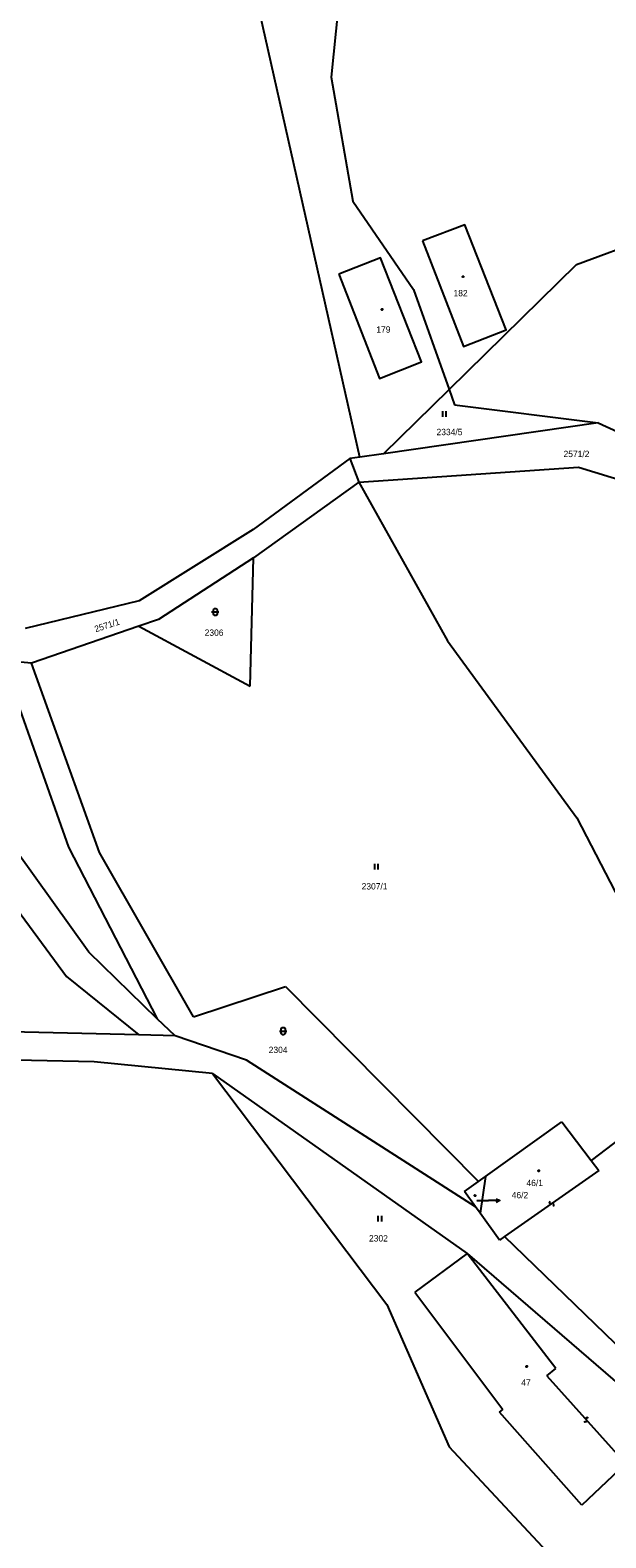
# Model space of a CAD drawing. Extents: x -747792 to -745414, y -1093712 to -1091463.
# Drawn here: x -746775.5 to -746698.3, y -1093052.6 to -1092850.4 of the extents above; entities that cross this region are included whole.
import ezdxf

# ---------------------------------------------------------------- set-up
doc = ezdxf.new("R2010")
doc.units = 0
for name, color, linetype in [('Budovy', 7, 'Continuous'), ('Doplňkové značky', 7, 'Continuous'), ('Koleje_dopravní prvky', 7, 'Continuous'), ('Kultury', 7, 'Continuous'), ('Ploty_opěrné zdi', 7, 'Continuous'), ('Stromy_porost', 7, 'Continuous')]:
    doc.layers.add(name, color=color, linetype=linetype)

msp = doc.modelspace()

# ---------------------------------------------------------------- linework, layer by layer
at = {"layer": 'Budovy'}
for points in [[(-746720.18, -1092901.53), (-746720.18, -1092902.28)], [(-746719.68, -1092902.28), (-746719.68, -1092901.53)], [(-746751.18, -1092928.44), (-746750.55, -1092928.44), (-746750.18, -1092928.44)], [(-746729.33, -1092962.21), (-746729.33, -1092962.96)], [(-746728.83, -1092962.96), (-746728.83, -1092962.21)], [(-746742.07, -1092984.65), (-746741.43, -1092984.65), (-746741.07, -1092984.65)], [(-746728.85, -1093009.42), (-746728.85, -1093010.17)], [(-746728.35, -1093010.17), (-746728.35, -1093009.42)]]:
    msp.add_lwpolyline(points, dxfattribs=at)
for points in [[(-746750.93, -1092928.19), (-746750.88, -1092928.04), (-746750.76, -1092927.96), (-746750.6, -1092927.96), (-746750.48, -1092928.04), (-746750.43, -1092928.19), (-746750.43, -1092928.69), (-746750.48, -1092928.83), (-746750.6, -1092928.92), (-746750.76, -1092928.92), (-746750.88, -1092928.83), (-746750.93, -1092928.69)], [(-746741.82, -1092984.4), (-746741.77, -1092984.26), (-746741.65, -1092984.17), (-746741.49, -1092984.17), (-746741.36, -1092984.26), (-746741.32, -1092984.4), (-746741.32, -1092984.9), (-746741.36, -1092985.04), (-746741.49, -1092985.13), (-746741.65, -1092985.13), (-746741.77, -1092985.04), (-746741.82, -1092984.9)]]:
    msp.add_lwpolyline(points, close=True, dxfattribs=at)
at = {"layer": 'Doplňkové značky'}
for points in [[(-746715.59, -1093007.35), (-746714.01, -1093007.37)], [(-746712.51, -1093007.39), (-746714.01, -1093007.37)], [(-746713.01, -1093007.13), (-746712.51, -1093007.39), (-746713.01, -1093007.63)]]:
    msp.add_lwpolyline(points, dxfattribs=at)
at = {"layer": 'Kultury'}
for points in [[(-746700.24, -1093001.99), (-746699.21, -1093003.36)], [(-746699.21, -1093003.36), (-746711.87, -1093012.22)], [(-746705.35, -1093008.11), (-746705.25, -1093007.98), (-746705.29, -1093007.82), (-746705.43, -1093007.75), (-746705.67, -1093007.82), (-746705.8, -1093007.74), (-746705.83, -1093007.58), (-746705.73, -1093007.47)], [(-746704.97, -1093029.92), (-746716.87, -1093014.48)], [(-746706.2, -1093030.87), (-746704.97, -1093029.92)], [(-746706.2, -1093030.87), (-746695.61, -1093042.69)], [(-746700.61, -1093036.55), (-746700.75, -1093036.47), (-746700.9, -1093036.53), (-746700.96, -1093036.67), (-746700.86, -1093036.91), (-746700.92, -1093037.04), (-746701.08, -1093037.09), (-746701.2, -1093037.01)]]:
    msp.add_lwpolyline(points, dxfattribs=at)
at = {"layer": 'Ploty_opěrné zdi'}
for points in [[(-746717.44, -1092883.4), (-746717.39, -1092883.41), (-746717.36, -1092883.45), (-746717.35, -1092883.48), (-746717.36, -1092883.52), (-746717.41, -1092883.56), (-746717.44, -1092883.56), (-746717.48, -1092883.55), (-746717.51, -1092883.52), (-746717.52, -1092883.48), (-746717.51, -1092883.44), (-746717.47, -1092883.4)], [(-746728.3, -1092887.79), (-746728.25, -1092887.8), (-746728.23, -1092887.85), (-746728.22, -1092887.88), (-746728.23, -1092887.92), (-746728.27, -1092887.96), (-746728.3, -1092887.96), (-746728.34, -1092887.95), (-746728.38, -1092887.92), (-746728.39, -1092887.88), (-746728.38, -1092887.83), (-746728.33, -1092887.8)], [(-746707.29, -1093003.3), (-746707.24, -1093003.31), (-746707.22, -1093003.36), (-746707.21, -1093003.39), (-746707.22, -1093003.44), (-746707.26, -1093003.47), (-746707.29, -1093003.47), (-746707.33, -1093003.46), (-746707.36, -1093003.43), (-746707.38, -1093003.39), (-746707.36, -1093003.34), (-746707.33, -1093003.31)], [(-746715.81, -1093006.62), (-746715.76, -1093006.64), (-746715.74, -1093006.68), (-746715.73, -1093006.71), (-746715.74, -1093006.76), (-746715.78, -1093006.79), (-746715.81, -1093006.79), (-746715.85, -1093006.78), (-746715.89, -1093006.75), (-746715.9, -1093006.71), (-746715.89, -1093006.67), (-746715.84, -1093006.63)], [(-746708.9, -1093029.54), (-746708.85, -1093029.55), (-746708.83, -1093029.6), (-746708.82, -1093029.63), (-746708.83, -1093029.67), (-746708.86, -1093029.71), (-746708.9, -1093029.71), (-746708.95, -1093029.7), (-746708.98, -1093029.67), (-746708.99, -1093029.63), (-746708.98, -1093029.58), (-746708.94, -1093029.55)]]:
    msp.add_lwpolyline(points, close=True, dxfattribs=at)
at = {"layer": 'Stromy_porost'}
for points in [[(-746731.28, -1092907.69), (-746745.88, -1092842.91)], [(-746733.89, -1092844.34), (-746735.11, -1092856.73)], [(-746735.11, -1092856.73), (-746732.21, -1092873.33)], [(-746702.19, -1092881.84), (-746673.9, -1092871.4)], [(-746732.21, -1092873.33), (-746724.1, -1092885.21)], [(-746719.31, -1092898.61), (-746702.19, -1092881.84)], [(-746724.1, -1092885.21), (-746719.31, -1092898.61)], [(-746728.11, -1092907.23), (-746719.31, -1092898.61)], [(-746719.31, -1092898.61), (-746718.58, -1092900.66)], [(-746718.58, -1092900.66), (-746699.3, -1092903.07)], [(-746699.3, -1092903.07), (-746728.11, -1092907.23)], [(-746699.3, -1092903.07), (-746674.17, -1092914.57)], [(-746731.28, -1092907.69), (-746732.62, -1092907.88)], [(-746728.11, -1092907.23), (-746731.28, -1092907.69)], [(-746732.62, -1092907.88), (-746745.58, -1092917.36)], [(-746732.62, -1092907.88), (-746731.42, -1092911.03)], [(-746731.42, -1092911.03), (-746701.96, -1092909.01)], [(-746701.96, -1092909.01), (-746676.22, -1092916.88)], [(-746731.42, -1092911.03), (-746745.53, -1092921.19)], [(-746731.42, -1092911.03), (-746719.5, -1092932.33)], [(-746745.58, -1092917.36), (-746760.87, -1092926.96)], [(-746745.53, -1092921.19), (-746758.3, -1092929.43)], [(-746745.98, -1092938.41), (-746745.53, -1092921.19)], [(-746760.87, -1092926.96), (-746776.17, -1092930.66)], [(-746758.3, -1092929.43), (-746760.93, -1092930.34)], [(-746804.57, -1092931.22), (-746770.64, -1092977.33)], [(-746760.93, -1092930.34), (-746775.35, -1092935.3)], [(-746760.93, -1092930.34), (-746745.98, -1092938.41)], [(-746767.65, -1092974.06), (-746796.79, -1092933.41)], [(-746719.5, -1092932.33), (-746702.15, -1092956.05)], [(-746775.35, -1092935.3), (-746779.23, -1092934.95)], [(-746779.23, -1092934.95), (-746770.35, -1092959.99)], [(-746766.23, -1092960.72), (-746775.35, -1092935.3)], [(-746702.15, -1092956.05), (-746689.35, -1092980.81)], [(-746770.35, -1092959.99), (-746758.46, -1092983.01)], [(-746753.58, -1092982.75), (-746766.23, -1092960.72)], [(-746758.46, -1092983.01), (-746767.65, -1092974.06)], [(-746770.64, -1092977.33), (-746760.94, -1092985.17)], [(-746753.58, -1092982.75), (-746741.24, -1092978.69)], [(-746741.24, -1092978.69), (-746715.36, -1093004.83)], [(-746760.94, -1092985.17), (-746826.08, -1092983.62)], [(-746756.05, -1092985.29), (-746758.46, -1092983.01)], [(-746756.05, -1092985.29), (-746760.94, -1092985.17)], [(-746746.49, -1092988.54), (-746756.05, -1092985.29)], [(-746766.93, -1092988.76), (-746821.71, -1092987.62)], [(-746715.77, -1093008.21), (-746746.49, -1092988.54)], [(-746751.04, -1092990.33), (-746766.93, -1092988.76)], [(-746751.04, -1092990.33), (-746727.68, -1093021.32)], [(-746751.04, -1092990.33), (-746716.87, -1093014.48)], [(-746714.44, -1093004.17), (-746704.16, -1092996.82)], [(-746704.16, -1092996.82), (-746700.24, -1093001.99)], [(-746693.49, -1092996.88), (-746700.24, -1093001.99)], [(-746717.23, -1093006.17), (-746715.36, -1093004.83)], [(-746715.36, -1093004.83), (-746714.44, -1093004.17)], [(-746714.44, -1093004.17), (-746715.15, -1093009.07)], [(-746715.77, -1093008.21), (-746717.23, -1093006.17)], [(-746715.15, -1093009.07), (-746715.77, -1093008.21)], [(-746712.55, -1093012.7), (-746715.15, -1093009.07)], [(-746711.87, -1093012.22), (-746712.55, -1093012.7)], [(-746682.11, -1093040.96), (-746711.87, -1093012.22)], [(-746716.87, -1093014.48), (-746723.9, -1093019.65)], [(-746716.87, -1093014.48), (-746685.62, -1093041.42)], [(-746723.9, -1093019.65), (-746712.1, -1093035.41)], [(-746727.68, -1093021.32), (-746719.31, -1093040.4)], [(-746712.56, -1093035.77), (-746712.1, -1093035.41)], [(-746701.51, -1093048.21), (-746712.56, -1093035.77)], [(-746698.65, -1093062.54), (-746719.31, -1093040.4)], [(-746696.51, -1093043.53), (-746701.51, -1093048.21)]]:
    msp.add_lwpolyline(points, dxfattribs=at)
for points in [[(-746722.89, -1092878.68), (-746717.38, -1092892.83), (-746711.66, -1092890.62), (-746717.21, -1092876.51)], [(-746734.09, -1092883.14), (-746728.64, -1092897.11), (-746722.99, -1092894.91), (-746728.5, -1092880.94)]]:
    msp.add_lwpolyline(points, close=True, dxfattribs=at)

# ---------------------------------------------------------------- texts
at = {"layer": 'Doplňkové značky'}
msp.add_text('46/2', height=0.85, dxfattribs=at).set_placement((-746710.9, -1093007.07))
at = {"layer": 'Koleje_dopravní prvky'}
for s, height, p in [('182', 0.85, (-746718.71, -1092886.1)), ('179', 0.85, (-746729.07, -1092890.99)), ('2334/5', 0.85, (-746720.99, -1092904.73)), ('2571/2', 0.85, (-746703.95, -1092907.67)), ('2306', 0.85, (-746752.1, -1092931.64)), ('2307/1', 0.85, (-746731.04, -1092965.66)), ('2304', 0.85, (-746743.51, -1092987.59)), ('46/1', 0.85, (-746708.92, -1093005.44)), ('46/2', 0.05, (-746715.67, -1093007.35)), ('2302', 0.85, (-746730.05, -1093012.87)), ('47', 0.85, (-746709.62, -1093032.21))]:
    msp.add_text(s, height=height, dxfattribs=at).set_placement(p)
msp.add_text('2571/1', height=0.85, rotation=17.819, dxfattribs=at).set_placement((-746766.73, -1092931.17))

doc.saveas('drawing.dxf')
